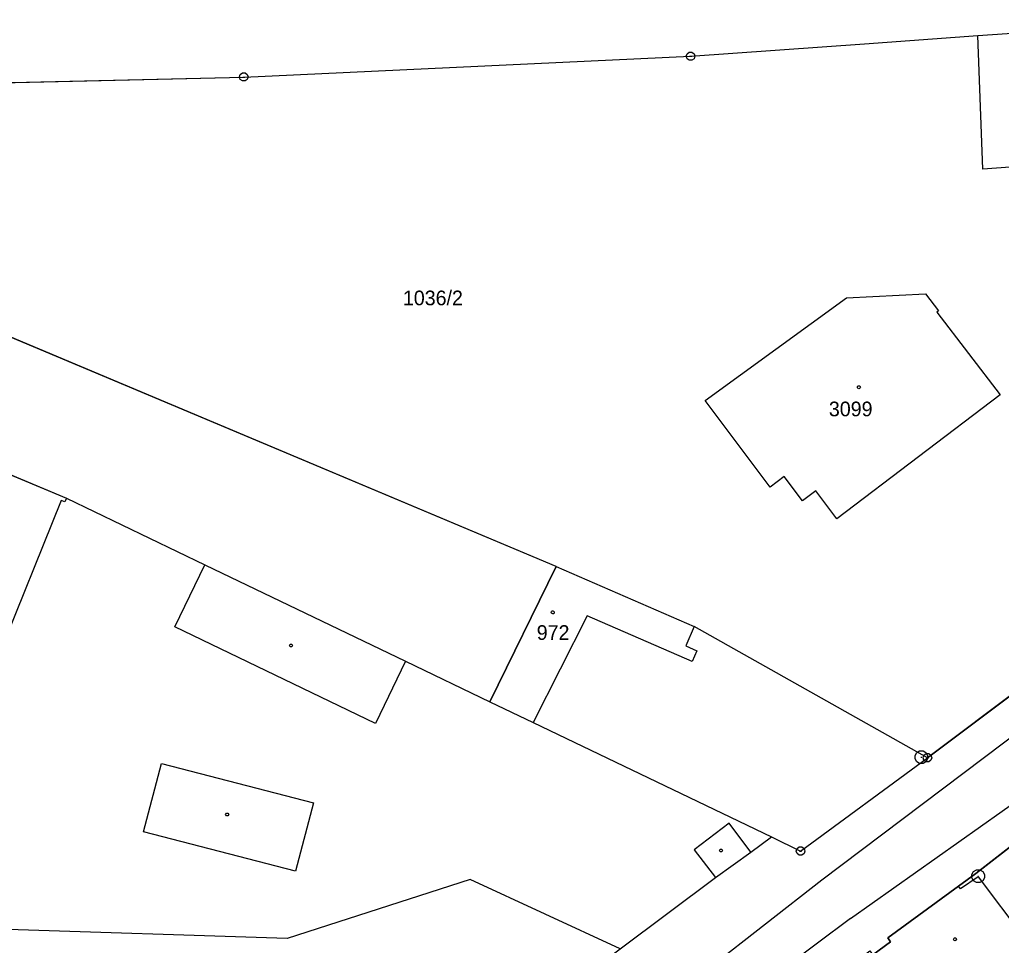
# Model space of a CAD drawing. Extents: x -777309 to -774195, y -1144706 to -1143600.
# Drawn here: x -775315.7 to -775201.9, y -1144569.6 to -1144462.3 of the extents above; entities that cross this region are included whole.
import ezdxf

# ---------------------------------------------------------------- set-up
doc = ezdxf.new("R2010")
doc.units = 0
for name, color, linetype in [('1', 7, 'Continuous'), ('11', 7, 'Continuous'), ('12', 7, 'Continuous'), ('2', 7, 'Continuous'), ('4', 7, 'Continuous'), ('5', 7, 'Continuous'), ('8', 7, 'Continuous')]:
    doc.layers.add(name, color=color, linetype=linetype)

msp = doc.modelspace()

# ---------------------------------------------------------------- linework, layer by layer
at = {"layer": '1'}
for p, q in [((-775204.62, -1144464.16), (-775201.24, -1144463.92)), ((-775237.91, -1144466.56), (-775217.76, -1144465.11)), ((-775217.76, -1144465.11), (-775204.62, -1144464.16)), ((-775204.06, -1144479.66), (-775204.62, -1144464.16)), ((-775289.7, -1144468.96), (-775237.91, -1144466.56)), ((-775332.79, -1144469.99), (-775289.7, -1144468.96)), ((-775253.51, -1144525.7), (-775380, -1144472.53)), ((-775196.81, -1144479.12), (-775204.06, -1144479.66)), ((-775236.21, -1144506.46), (-775219.83, -1144494.54)), ((-775219.83, -1144494.54), (-775210.69, -1144494.08)), ((-775210.69, -1144494.08), (-775209.18, -1144496.06)), ((-775209.18, -1144496.06), (-775209.38, -1144496.21)), ((-775209.38, -1144496.21), (-775202.05, -1144505.82)), ((-775202.05, -1144505.82), (-775220.96, -1144520.19)), ((-775228.69, -1144516.49), (-775236.21, -1144506.46)), ((-775328.85, -1144510.01), (-775310.26, -1144517.79)), ((-775227.07, -1144515.28), (-775228.69, -1144516.49)), ((-775224.95, -1144518.11), (-775227.07, -1144515.28)), ((-775223.39, -1144516.95), (-775224.95, -1144518.11)), ((-775220.96, -1144520.19), (-775223.39, -1144516.95)), ((-775310.26, -1144517.79), (-775294.22, -1144525.5)), ((-775294.22, -1144525.5), (-775270.96, -1144536.68)), ((-775253.51, -1144525.7), (-775261.18, -1144541.39)), ((-775253.51, -1144525.7), (-775237.49, -1144532.67)), ((-775210.47, -1144547.88), (-775237.49, -1144532.67)), ((-775189.95, -1144532.5), (-775210.47, -1144547.88)), ((-775270.96, -1144536.68), (-775261.18, -1144541.39)), ((-775261.18, -1144541.39), (-775256.17, -1144543.79)), ((-775256.17, -1144543.79), (-775228.56, -1144557.06)), ((-775225.17, -1144558.7), (-775210.47, -1144547.88)), ((-775195.74, -1144554.22), (-775204.87, -1144561.28)), ((-775230.93, -1144558.83), (-775228.56, -1144557.06)), ((-775228.56, -1144557.06), (-775225.17, -1144558.7)), ((-775235.05, -1144561.78), (-775230.93, -1144558.83)), ((-775246.07, -1144570.05), (-775235.05, -1144561.78)), ((-775204.87, -1144561.28), (-775206.87, -1144562.75)), ((-775204.58, -1144561.67), (-775206.63, -1144563.07)), ((-775204.58, -1144561.67), (-775197.93, -1144570.55)), ((-775263.45, -1144562.01), (-775284.69, -1144568.85)), ((-775246.07, -1144570.05), (-775263.45, -1144562.01)), ((-775206.87, -1144562.75), (-775215.07, -1144568.77)), ((-775206.63, -1144563.07), (-775206.87, -1144562.75)), ((-775284.69, -1144568.85), (-775330.85, -1144567.36)), ((-775215.07, -1144568.77), (-775214.74, -1144569.21)), ((-775214.74, -1144569.21), (-775216.8, -1144570.72))]:
    msp.add_line(p, q, dxfattribs=at)
at = {"layer": '11'}
for points in [[(-775493.48, -1144455.3), (-775445.43, -1144461.73), (-775435.74, -1144465.74), (-775366.41, -1144494.44), (-775328.85, -1144510.01), (-775310.26, -1144517.79), (-775294.22, -1144525.5), (-775270.96, -1144536.68), (-775261.18, -1144541.39), (-775253.51, -1144525.7), (-775380, -1144472.53), (-775389.68, -1144468.46), (-775332.79, -1144469.99), (-775289.7, -1144468.96), (-775237.91, -1144466.56), (-775217.76, -1144465.11), (-775204.62, -1144464.16), (-775201.24, -1144463.92), (-775148.23, -1144459.85)], [(-775428.93, -1144700), (-775407.43, -1144686.48), (-775390, -1144675.91), (-775354.18, -1144649.53), (-775318.59, -1144623.31), (-775317.85, -1144622.66), (-775257.86, -1144578.79), (-775246.07, -1144570.05), (-775235.05, -1144561.78), (-775230.93, -1144558.83), (-775228.56, -1144557.06), (-775225.17, -1144558.7), (-775210.47, -1144547.88), (-775189.95, -1144532.5), (-775159.15, -1144509.7)], [(-775206.87, -1144562.75), (-775204.87, -1144561.28), (-775195.74, -1144554.22), (-775193.87, -1144552.76), (-775193.68, -1144552.99), (-775188.17, -1144548.88), (-775180.84, -1144543.5), (-775171.89, -1144536.82), (-775163.04, -1144530.28), (-775154.12, -1144523.75)], [(-775320.64, -1144646.86), (-775315.54, -1144643.07), (-775315.63, -1144642.95), (-775311.83, -1144640.13), (-775311.74, -1144640.25), (-775307.84, -1144637.35), (-775294.95, -1144627.78), (-775285.39, -1144620.71), (-775281.93, -1144618.14), (-775282.02, -1144618.02), (-775278.17, -1144615.17), (-775278.08, -1144615.29), (-775274.06, -1144612.3), (-775269.14, -1144608.66), (-775261.98, -1144603.34), (-775252.95, -1144596.66), (-775244.08, -1144590.11), (-775234.89, -1144583.32), (-775226.12, -1144576.88), (-775217.13, -1144570.28), (-775216.8, -1144570.72), (-775214.74, -1144569.21), (-775215.07, -1144568.77), (-775206.87, -1144562.75)]]:
    msp.add_lwpolyline(points, dxfattribs=at)
at = {"layer": '12'}
for p, q in [((-775236.21, -1144506.46), (-775219.83, -1144494.54)), ((-775219.83, -1144494.54), (-775210.69, -1144494.08)), ((-775210.69, -1144494.08), (-775209.18, -1144496.06)), ((-775209.18, -1144496.06), (-775209.38, -1144496.21)), ((-775209.38, -1144496.21), (-775202.05, -1144505.82)), ((-775202.05, -1144505.82), (-775220.96, -1144520.19)), ((-775228.69, -1144516.49), (-775236.21, -1144506.46)), ((-775328.85, -1144510.01), (-775310.26, -1144517.79)), ((-775227.07, -1144515.28), (-775228.69, -1144516.49)), ((-775224.95, -1144518.11), (-775227.07, -1144515.28)), ((-775223.39, -1144516.95), (-775224.95, -1144518.11)), ((-775220.96, -1144520.19), (-775223.39, -1144516.95)), ((-775310.85, -1144518.04), (-775325.78, -1144554.96)), ((-775310.43, -1144518.21), (-775310.85, -1144518.04)), ((-775310.26, -1144517.79), (-775310.43, -1144518.21)), ((-775253.51, -1144525.7), (-775261.18, -1144541.39)), ((-775253.51, -1144525.7), (-775237.49, -1144532.67)), ((-775249.91, -1144531.42), (-775256.17, -1144543.79)), ((-775237.73, -1144536.72), (-775249.91, -1144531.42)), ((-775237.49, -1144532.67), (-775238.47, -1144534.91)), ((-775238.47, -1144534.91), (-775237.19, -1144535.47)), ((-775237.19, -1144535.47), (-775237.73, -1144536.72)), ((-775261.18, -1144541.39), (-775256.17, -1144543.79)), ((-775204.58, -1144561.67), (-775206.63, -1144563.07)), ((-775204.58, -1144561.67), (-775197.93, -1144570.55)), ((-775206.87, -1144562.75), (-775215.07, -1144568.77)), ((-775206.63, -1144563.07), (-775206.87, -1144562.75)), ((-775215.07, -1144568.77), (-775214.74, -1144569.21)), ((-775214.74, -1144569.21), (-775216.8, -1144570.72))]:
    msp.add_line(p, q, dxfattribs=at)
at = {"layer": '4'}
for p, q in [((-775222.72, -1144562.02), (-775118.85, -1144483.61)), ((-775219.39, -1144566.53), (-775132.72, -1144505.09)), ((-775310.85, -1144518.04), (-775325.78, -1144554.96)), ((-775310.43, -1144518.21), (-775310.85, -1144518.04)), ((-775310.26, -1144517.79), (-775310.43, -1144518.21)), ((-775297.69, -1144532.71), (-775294.22, -1144525.5)), ((-775249.91, -1144531.42), (-775256.17, -1144543.79)), ((-775237.73, -1144536.72), (-775249.91, -1144531.42)), ((-775274.43, -1144543.89), (-775297.69, -1144532.71)), ((-775237.49, -1144532.67), (-775238.47, -1144534.91)), ((-775238.47, -1144534.91), (-775237.19, -1144535.47)), ((-775237.19, -1144535.47), (-775237.73, -1144536.72)), ((-775270.96, -1144536.68), (-775274.43, -1144543.89)), ((-775301.31, -1144556.46), (-775299.25, -1144548.54)), ((-775299.25, -1144548.54), (-775281.64, -1144553.11)), ((-775281.64, -1144553.11), (-775283.69, -1144561.02)), ((-775233.45, -1144555.48), (-775237.5, -1144558.55)), ((-775230.93, -1144558.83), (-775233.45, -1144555.48)), ((-775283.69, -1144561.02), (-775301.31, -1144556.46)), ((-775237.5, -1144558.55), (-775235.05, -1144561.78)), ((-775269.86, -1144598.82), (-775222.72, -1144562.02)), ((-775219.39, -1144566.53), (-775352.58, -1144665.72))]:
    msp.add_line(p, q, dxfattribs=at)
at = {"layer": '5'}
for points in [[(-775218.41, -1144504.75), (-775218.31, -1144504.77), (-775218.26, -1144504.86), (-775218.24, -1144504.92), (-775218.26, -1144505.01), (-775218.34, -1144505.08), (-775218.41, -1144505.09), (-775218.5, -1144505.06), (-775218.56, -1144505), (-775218.58, -1144504.92), (-775218.56, -1144504.83), (-775218.48, -1144504.76)], [(-775253.89, -1144530.85), (-775253.79, -1144530.87), (-775253.74, -1144530.96), (-775253.72, -1144531.02), (-775253.74, -1144531.11), (-775253.82, -1144531.18), (-775253.89, -1144531.19), (-775253.98, -1144531.16), (-775254.04, -1144531.1), (-775254.06, -1144531.02), (-775254.04, -1144530.93), (-775253.96, -1144530.86)], [(-775284.14, -1144534.71), (-775284.05, -1144534.86), (-775284.14, -1144535.01), (-775284.32, -1144535.01), (-775284.41, -1144534.86), (-775284.32, -1144534.71)], [(-775291.54, -1144554.3), (-775291.45, -1144554.45), (-775291.54, -1144554.6), (-775291.72, -1144554.6), (-775291.81, -1144554.45), (-775291.72, -1144554.3)], [(-775234.31, -1144558.48), (-775234.22, -1144558.63), (-775234.31, -1144558.78), (-775234.49, -1144558.78), (-775234.58, -1144558.63), (-775234.49, -1144558.48)], [(-775207.27, -1144568.75), (-775207.17, -1144568.77), (-775207.12, -1144568.86), (-775207.1, -1144568.92), (-775207.12, -1144569.01), (-775207.2, -1144569.08), (-775207.27, -1144569.09), (-775207.36, -1144569.06), (-775207.42, -1144569), (-775207.44, -1144568.92), (-775207.42, -1144568.83), (-775207.34, -1144568.76)]]:
    msp.add_lwpolyline(points, close=True, dxfattribs=at)
at = {"layer": '8'}
for p, q in [((-775238.03, -1144466.56), (-775237.79, -1144466.56)), ((-775289.82, -1144468.96), (-775289.58, -1144468.96)), ((-775211.22, -1144547.81), (-775211.12, -1144547.81)), ((-775210.59, -1144547.88), (-775210.35, -1144547.88)), ((-775225.29, -1144558.7), (-775225.05, -1144558.7)), ((-775204.64, -1144561.61), (-775204.54, -1144561.61))]:
    msp.add_line(p, q, dxfattribs=at)
for points in [[(-775237.76, -1144466.08), (-775237.51, -1144466.26), (-775237.41, -1144466.55), (-775237.51, -1144466.84), (-775237.76, -1144467.02), (-775238.07, -1144467.02), (-775238.32, -1144466.84), (-775238.42, -1144466.55), (-775238.32, -1144466.26), (-775238.07, -1144466.08)], [(-775289.55, -1144468.48), (-775289.3, -1144468.66), (-775289.2, -1144468.95), (-775289.3, -1144469.24), (-775289.55, -1144469.42), (-775289.86, -1144469.42), (-775290.11, -1144469.24), (-775290.21, -1144468.95), (-775290.11, -1144468.66), (-775289.86, -1144468.48)], [(-775210.98, -1144547.09), (-775210.64, -1144547.28), (-775210.45, -1144547.62), (-775210.45, -1144548.01), (-775210.64, -1144548.35), (-775210.98, -1144548.54), (-775211.37, -1144548.54), (-775211.71, -1144548.35), (-775211.9, -1144548.01), (-775211.9, -1144547.62), (-775211.71, -1144547.28), (-775211.37, -1144547.09)], [(-775210.32, -1144547.4), (-775210.07, -1144547.58), (-775209.97, -1144547.87), (-775210.07, -1144548.16), (-775210.32, -1144548.34), (-775210.63, -1144548.34), (-775210.88, -1144548.16), (-775210.98, -1144547.87), (-775210.88, -1144547.58), (-775210.63, -1144547.4)], [(-775225.02, -1144558.22), (-775224.77, -1144558.4), (-775224.67, -1144558.69), (-775224.77, -1144558.98), (-775225.02, -1144559.16), (-775225.33, -1144559.16), (-775225.58, -1144558.98), (-775225.68, -1144558.69), (-775225.58, -1144558.4), (-775225.33, -1144558.22)], [(-775204.4, -1144560.89), (-775204.06, -1144561.08), (-775203.87, -1144561.42), (-775203.87, -1144561.81), (-775204.06, -1144562.15), (-775204.4, -1144562.34), (-775204.79, -1144562.34), (-775205.13, -1144562.15), (-775205.32, -1144561.81), (-775205.32, -1144561.42), (-775205.13, -1144561.08), (-775204.79, -1144560.89)]]:
    msp.add_lwpolyline(points, close=True, dxfattribs=at)

# ---------------------------------------------------------------- texts
at = {"layer": '2'}
for s, p in [('1036/2', (-775271.26, -1144495.42)), ('3099', (-775221.89, -1144508.29)), ('972', (-775255.75, -1144534.21))]:
    msp.add_text(s, height=1.7, dxfattribs=at).set_placement(p)

doc.saveas('drawing.dxf')
